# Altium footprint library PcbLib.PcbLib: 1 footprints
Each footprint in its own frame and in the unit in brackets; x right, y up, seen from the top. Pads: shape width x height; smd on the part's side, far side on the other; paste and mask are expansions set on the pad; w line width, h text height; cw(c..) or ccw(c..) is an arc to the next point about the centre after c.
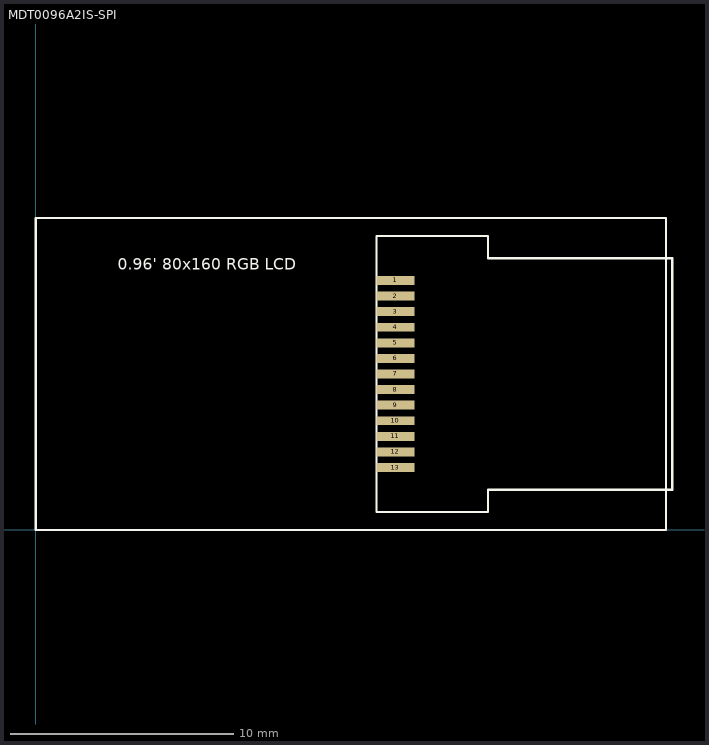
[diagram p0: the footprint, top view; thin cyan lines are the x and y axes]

## MDT0096A2IS-SPI [mm]
height 1.53
pads (13):
  rect 1.7x0.4 smd: 1(16.15,11.2) 2(16.15,10.5) 3(16.15,9.8) 4(16.15,9.1) 5(16.15,8.4) 6(16.15,7.7) 7(16.15,7) 8(16.15,6.3) 9(16.15,5.6) 10(16.15,4.9) 11(16.15,4.2) 12(16.15,3.5) 13(16.15,2.8)
Top Overlay:
  lines w0.102: 0,0 0,14 28.3,14 28.3,0 0,0 ; 15.3,0.8 15.3,13.2 20.3,13.2 20.3,12.2 28.575,12.2 28.575,1.8 20.3,1.8 20.3,0.8 15.3,0.8
  text "0.96' 80x160 RGB LCD" at 3.683,11.684 h0.5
